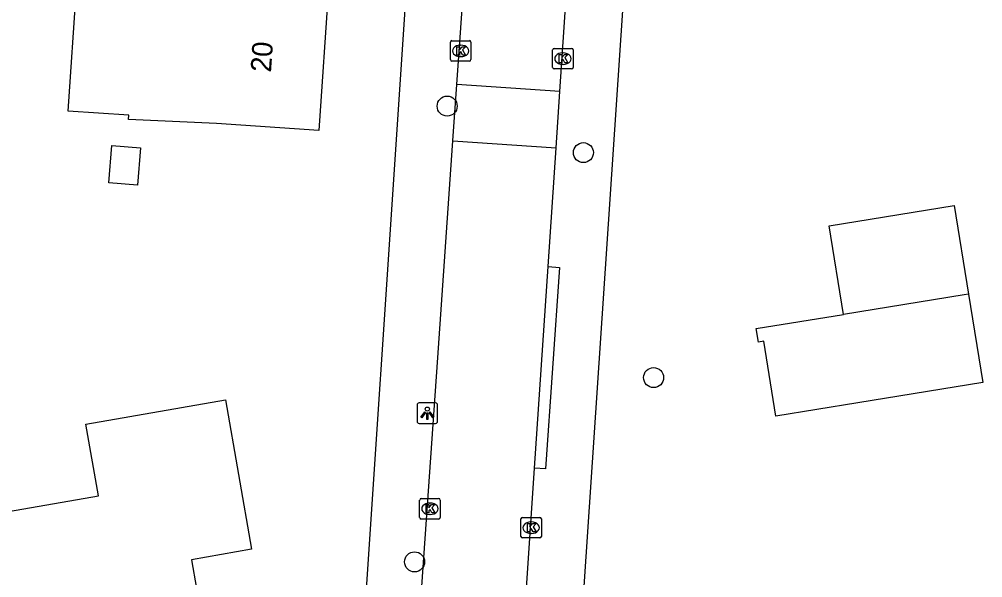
# Model space of a CAD drawing. Extents: x 161772 to 163123, y 383092 to 383917.
# Drawn here: x 162297.59 to 162344.61, y 383673.53 to 383700.79 of the extents above; entities that cross this region are included whole.
import ezdxf

# ---------------------------------------------------------------- set-up
doc = ezdxf.new("R2010")
doc.units = 0
for name, color, linetype in [('IMGEO_Boom', 7, 'Continuous'), ('IMGEO_Kolk', 7, 'Continuous'), ('IMGEO_Lichtpunt', 7, 'Continuous'), ('IMGEO_Pand', 7, 'Continuous'), ('IMGEO_Pand_nummerreeks', 7, 'Continuous'), ('IMGEO_Rijbaan_lokaal_open', 7, 'Continuous'), ('IMGEO_Voetpad_open', 7, 'Continuous')]:
    doc.layers.add(name, color=color, linetype=linetype)

msp = doc.modelspace()

# ---------------------------------------------------------------- linework, layer by layer
at = {"layer": 'IMGEO_Boom'}
for centre in [(162318.474, 383696.551), (162325.122, 383694.279), (162328.551, 383683.299), (162316.883, 383674.303)]:
    msp.add_circle(centre, 0.489, dxfattribs=at)
at = {"layer": 'IMGEO_Kolk'}
for p, q in [((162318.706, 383699.745), (162319.558, 383699.745)), ((162318.631, 383698.819), (162318.631, 383699.671)), ((162319.119, 383699.525), (162319.144, 383699.525)), ((162319.632, 383699.671), (162319.632, 383698.819)), ((162323.623, 383698.442), (162323.623, 383699.294)), ((162323.698, 383699.368), (162324.55, 383699.368)), ((162324.624, 383699.294), (162324.624, 383698.442)), ((162319.142, 383698.965), (162319.117, 383698.965)), ((162324.111, 383699.148), (162324.136, 383699.148)), ((162319.558, 383698.745), (162318.706, 383698.745)), ((162324.55, 383698.368), (162323.698, 383698.368)), ((162324.134, 383698.588), (162324.109, 383698.588)), ((162317.131, 383676.47), (162317.131, 383677.322)), ((162317.206, 383677.396), (162318.058, 383677.396)), ((162317.619, 383677.176), (162317.644, 383677.176)), ((162318.132, 383677.322), (162318.132, 383676.47)), ((162318.058, 383676.396), (162317.206, 383676.396)), ((162317.642, 383676.616), (162317.617, 383676.616)), ((162322.072, 383675.545), (162322.072, 383676.397)), ((162322.147, 383676.471), (162322.999, 383676.471)), ((162322.56, 383676.251), (162322.585, 383676.251)), ((162323.073, 383676.397), (162323.073, 383675.545)), ((162322.999, 383675.471), (162322.147, 383675.471)), ((162322.583, 383675.691), (162322.558, 383675.691))]:
    msp.add_line(p, q, dxfattribs=at)
for points in [[(162318.706, 383699.745), (162319.558, 383699.745)], [(162318.631, 383698.819), (162318.631, 383699.671)], [(162318.952, 383699.445), (162319.075, 383699.445), (162319.075, 383699.294), (162319.205, 383699.445), (162319.369, 383699.445), (162319.223, 383699.294), (162319.376, 383699.045), (162319.224, 383699.045), (162319.139, 383699.209), (162319.075, 383699.142), (162319.075, 383699.045), (162318.952, 383699.045), (162318.952, 383699.445)], [(162319.632, 383699.671), (162319.632, 383698.819)], [(162323.623, 383698.442), (162323.623, 383699.294)], [(162323.698, 383699.368), (162324.55, 383699.368)], [(162324.624, 383699.294), (162324.624, 383698.442)], [(162323.944, 383699.068), (162324.067, 383699.068), (162324.067, 383698.917), (162324.197, 383699.068), (162324.361, 383699.068), (162324.215, 383698.917), (162324.368, 383698.668), (162324.216, 383698.668), (162324.131, 383698.832), (162324.067, 383698.765), (162324.067, 383698.668), (162323.944, 383698.668), (162323.944, 383699.068)], [(162319.558, 383698.745), (162318.706, 383698.745)], [(162324.55, 383698.368), (162323.698, 383698.368)], [(162317.131, 383676.47), (162317.131, 383677.322)], [(162317.206, 383677.396), (162318.058, 383677.396)], [(162318.132, 383677.322), (162318.132, 383676.47)], [(162317.452, 383677.096), (162317.575, 383677.096), (162317.575, 383676.945), (162317.705, 383677.096), (162317.869, 383677.096), (162317.723, 383676.945), (162317.876, 383676.696), (162317.724, 383676.696), (162317.639, 383676.86), (162317.575, 383676.793), (162317.575, 383676.696), (162317.452, 383676.696), (162317.452, 383677.096)], [(162318.058, 383676.396), (162317.206, 383676.396)], [(162322.072, 383675.545), (162322.072, 383676.397)], [(162322.147, 383676.471), (162322.999, 383676.471)], [(162323.073, 383676.397), (162323.073, 383675.545)], [(162322.393, 383676.171), (162322.516, 383676.171), (162322.516, 383676.02), (162322.646, 383676.171), (162322.81, 383676.171), (162322.664, 383676.02), (162322.817, 383675.771), (162322.665, 383675.771), (162322.58, 383675.935), (162322.516, 383675.868), (162322.516, 383675.771), (162322.393, 383675.771), (162322.393, 383676.171)], [(162322.999, 383675.471), (162322.147, 383675.471)]]:
    msp.add_lwpolyline(points, dxfattribs=at)
for centre, start, end in [((162318.708, 383699.669), 91.552, 178.448), ((162318.708, 383699.669), 91.552, 178.448), ((162319.556, 383699.669), 1.552, 88.448), ((162319.556, 383699.669), 1.552, 88.448), ((162323.7, 383699.292), 91.552, 178.448), ((162323.7, 383699.292), 91.552, 178.448), ((162324.548, 383699.292), 1.552, 88.448), ((162324.548, 383699.292), 1.552, 88.448), ((162318.708, 383698.821), 181.552, 268.448), ((162318.708, 383698.821), 181.552, 268.448), ((162319.556, 383698.821), 271.552, 358.448), ((162319.556, 383698.821), 271.552, 358.448), ((162323.7, 383698.444), 181.552, 268.448), ((162323.7, 383698.444), 181.552, 268.448), ((162324.548, 383698.444), 271.552, 358.448), ((162324.548, 383698.444), 271.552, 358.448), ((162317.208, 383677.32), 91.552, 178.448), ((162317.208, 383677.32), 91.552, 178.448), ((162318.056, 383677.32), 1.552, 88.448), ((162318.056, 383677.32), 1.552, 88.448), ((162317.208, 383676.472), 181.552, 268.448), ((162317.208, 383676.472), 181.552, 268.448), ((162318.056, 383676.472), 271.552, 358.448), ((162318.056, 383676.472), 271.552, 358.448), ((162322.149, 383676.395), 91.552, 178.448), ((162322.149, 383676.395), 91.552, 178.448), ((162322.997, 383676.395), 1.552, 88.448), ((162322.997, 383676.395), 1.552, 88.448), ((162322.149, 383675.547), 181.552, 268.448), ((162322.149, 383675.547), 181.552, 268.448), ((162322.997, 383675.547), 271.552, 358.448), ((162322.997, 383675.547), 271.552, 358.448)]:
    msp.add_arc(centre, 0.0765, start, end, dxfattribs=at)
for centre, major_axis, ratio, start_param, end_param in [((162319.118, 383699.245), (-0.387, 0.002), 0.722429, 4.712389, 7.853982), ((162319.143, 383699.245), (-0.39, 0.002), 0.717154, 1.570796, 4.712389), ((162324.11, 383698.868), (-0.387, 0.002), 0.722429, 4.712389, 7.853982), ((162324.135, 383698.868), (-0.39, 0.002), 0.717154, 1.570796, 4.712389), ((162317.618, 383676.896), (-0.387, 0.002), 0.722429, 4.712389, 7.853982), ((162317.643, 383676.896), (-0.39, 0.002), 0.717154, 1.570796, 4.712389), ((162322.559, 383675.971), (-0.387, 0.002), 0.722429, 4.712389, 7.853982), ((162322.584, 383675.971), (-0.39, 0.002), 0.717154, 1.570796, 4.712389)]:
    msp.add_ellipse(centre, major_axis=major_axis, ratio=ratio, start_param=start_param, end_param=end_param, dxfattribs=at)
at = {"layer": 'IMGEO_Lichtpunt'}
for p, q in [((162317.007, 383681.965), (162317.007, 383681.158)), ((162317.007, 383681.965), (162317.007, 383681.158)), ((162317.909, 383682.06), (162317.101, 383682.06)), ((162317.909, 383682.06), (162317.101, 383682.06)), ((162318.003, 383681.158), (162318.003, 383681.965)), ((162318.003, 383681.158), (162318.003, 383681.965)), ((162317.101, 383681.064), (162317.909, 383681.064)), ((162317.101, 383681.064), (162317.909, 383681.064))]:
    msp.add_line(p, q, dxfattribs=at)
for points in [[(162317.381, 383681.629), (162317.42, 383681.601), (162317.232, 383681.339), (162317.194, 383681.366), (162317.381, 383681.629)], [(162317.483, 383681.581), (162317.53, 383681.581), (162317.53, 383681.259), (162317.483, 383681.259), (162317.483, 383681.581)], [(162317.593, 383681.601), (162317.631, 383681.628), (162317.818, 383681.366), (162317.779, 383681.338), (162317.593, 383681.601)]]:
    msp.add_lwpolyline(points, dxfattribs=at)
msp.add_circle((162317.506, 383681.763), 0.0994, dxfattribs=at)
for centre, start, end in [((162317.101, 383681.965), 90, 180), ((162317.101, 383681.965), 90, 180), ((162317.909, 383681.965), 0, 90), ((162317.909, 383681.965), 0, 90), ((162317.101, 383681.158), 180, 270), ((162317.101, 383681.158), 180, 270), ((162317.909, 383681.158), 270, 0), ((162317.909, 383681.158), 270, 360)]:
    msp.add_arc(centre, 0.0946, start, end, dxfattribs=at)
at = {"layer": 'IMGEO_Pand'}
for points in [[(162312.679, 383702.308), (162312.208, 383695.359), (162307.22, 383695.697), (162302.923, 383695.892), (162302.938, 383696.111), (162299.978, 383696.311), (162300.384, 383702.301), (162300.44, 383703.136)], [(162303.498, 383694.517), (162303.353, 383692.694), (162301.957, 383692.805), (162302.103, 383694.628), (162303.498, 383694.517)], [(162337.824, 383686.385), (162337.124, 383690.704), (162343.215, 383691.692), (162343.915, 383687.372)], [(162343.915, 383687.372), (162344.615, 383683.054), (162338.524, 383682.066), (162334.517, 383681.412), (162333.923, 383685.074), (162333.667, 383685.033), (162333.56, 383685.694), (162337.824, 383686.385)], [(162343.915, 383687.372), (162343.712, 383687.339), (162337.824, 383686.385)], [(162307.651, 383682.214), (162308.927, 383674.919), (162305.994, 383674.406), (162306.24, 383673.004), (162306.907, 383673.12), (162306.917, 383673.064), (162309.3, 383659.431), (162303.773, 383658.465), (162304.013, 383657.092), (162299.587, 383656.307), (162299.345, 383657.691), (162298.46, 383657.536), (162298.313, 383658.375), (162296.597, 383658.075), (162295.878, 383662.189), (162297.568, 383662.485), (162296.678, 383667.583), (162294.103, 383667.133), (162292.555, 383675.979), (162301.449, 383677.535), (162300.839, 383681.022), (162307.651, 383682.214)]]:
    msp.add_lwpolyline(points, dxfattribs=at)
at = {"layer": 'IMGEO_Rijbaan_lokaal_open'}
for points in [[(162323.98, 383697.26), (162325.296, 383716.851)], [(162318.944, 383697.598), (162319.639, 383707.534)], [(162318.752, 383694.86), (162318.944, 383697.598)], [(162323.98, 383697.26), (162318.944, 383697.598)], [(162323.796, 383694.521), (162323.98, 383697.26)], [(162316.164, 383657.756), (162318.027, 383684.506), (162318.752, 383694.86)], [(162318.752, 383694.86), (162323.796, 383694.521)], [(162323.406, 383688.717), (162323.796, 383694.521)], [(162322.744, 383678.877), (162323.406, 383688.717)], [(162321.3, 383657.411), (162322.744, 383678.877)]]:
    msp.add_lwpolyline(points, dxfattribs=at)
at = {"layer": 'IMGEO_Voetpad_open'}
for points in [[(162334.385, 383803.507), (162330.73, 383750), (162329.933, 383738.33), (162329.513, 383738.311), (162323.298, 383645.721), (162324.273, 383644.745)], [(162310.606, 383642.128), (162312.79, 383644.774), (162313.196, 383652.957), (162317.249, 383713.725), (162319.862, 383750), (162321.727, 383778.3), (162322.139, 383797.223)], [(162323.406, 383688.717), (162323.962, 383688.68), (162323.277, 383678.842), (162322.744, 383678.877)]]:
    msp.add_lwpolyline(points, dxfattribs=at)

# ---------------------------------------------------------------- texts
at = {"layer": 'IMGEO_Pand_nummerreeks'}
msp.add_text('20', height=1, rotation=86.1254, dxfattribs=at).set_placement((162309.874, 383698.181))

doc.saveas('drawing.dxf')
